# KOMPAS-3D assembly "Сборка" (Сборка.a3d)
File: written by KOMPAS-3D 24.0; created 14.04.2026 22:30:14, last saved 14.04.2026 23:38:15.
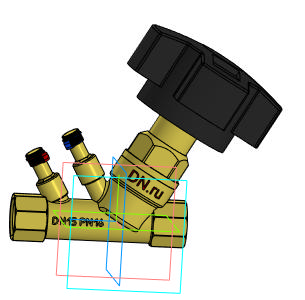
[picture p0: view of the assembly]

Document properties: Автор: tyuri; Полное имя файла: D:\Аутсорс\VB0000P-T Клапан балансировочный статический DN.ru\DN15\Исходные файлы\Сборка.a3d

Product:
- Component [detail]: Деталь1  | qty 1  | Автор: tyuri; additional columns: Типовые; source file: Деталь1 - Деталь1.m3d
- Body: Тело 1  | qty 1
    Масса: 0.34121
- Component [detail]: Ручка  | designation Деталь2  | qty 1  | Масса: 0.541971; Автор: tyuri; additional columns: Типовые; source file: Деталь2 - Деталь2.m3d
- Part/product: Сборка
    Масса: 0.883181

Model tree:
1. Эскиз:2  (labels: Ребро.Твердое тело1; Грань.Твердое тело1)
2. Элемент вращения:1  (labels: Грань.Твердое тело1)
     Угол 1 = 360
3. Смещенная плоскость:1
     Расстояние = 40
4. Эскиз:3  (with: Ребро.Элемент вращения:1)
5. Элемент выдавливания:1  (with: Грань.Элемент вращения:1)
     Расстояние 1 = -26.0177; Смещение 1 = 0.01
6. Эскиз:4
7. Элемент выдавливания:2  (with: Грань.Элемент вращения:1, Ребро.Элемент вращения:1)  (labels: Грань.Твердое тело1; Ребро.Твердое тело1; Твердое тело1)
     Расстояние 1 = -31.0088; Смещение 1 = 0.001; Ориентация = 2; Расстояние = 10

Referenced files in D:\Аутсорс\VB0000P-T Клапан балансировочный статический DN.ru\DN15\Исходные файлы\: Деталь1 - Деталь1.m3d, Деталь2 - Деталь2.m3d
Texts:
  DN15 PN16
  GOST 26.020 Pr3
  Деталь1 Деталь1
  Деталь2 Ручка
  Ось X.Начало координат
  Ось Z.Начало координат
